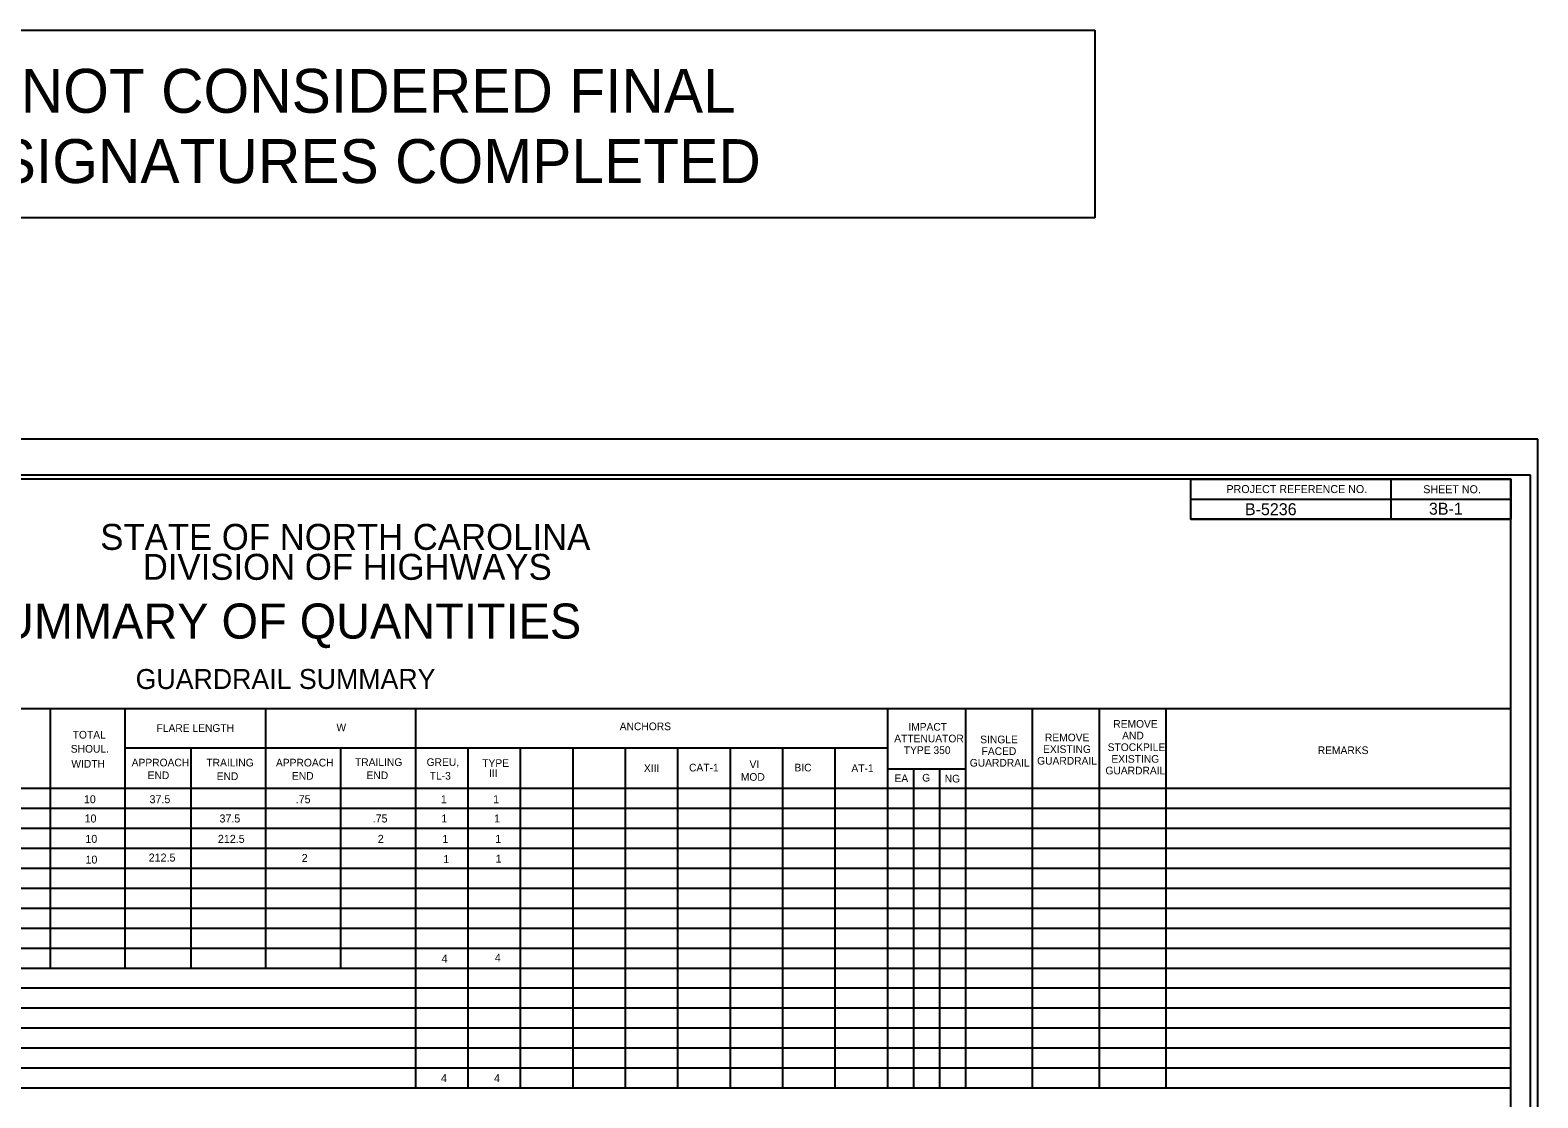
# Model space of a CAD drawing. Extents: x 9833 to 11517, y 9975 to 11331.
# Drawn here: x 10574 to 11517, y 10663 to 11331 of the extents above; entities that cross this region are included whole.
import ezdxf

# ---------------------------------------------------------------- set-up
doc = ezdxf.new("R2010")
doc.units = 0
for name, color, linetype in [('Old_Level_1', 7, 'Continuous'), ('Prop Dimension Text', 7, 'Continuous'), ('Sheet Cutting Line CELL', 7, 'Continuous'), ('Sheet Data Field CELL', 7, 'Continuous'), ('Sheet Plot Border Inside CELL', 7, 'Continuous'), ('Sheet Plot Border Outside CELL', 7, 'Continuous'), ('Sheet Sticker Exception Certification CELL', 7, 'Continuous'), ('Sheet Summary CELL', 7, 'Continuous'), ('Sheet Summary Combination CELL', 7, 'Continuous'), ('Sheet Summary Combination Grid CELL', 7, 'Continuous')]:
    doc.layers.add(name, color=color, linetype=linetype)

msp = doc.modelspace()

# ---------------------------------------------------------------- linework, layer by layer
at = {"layer": 'Sheet Cutting Line CELL'}
msp.add_line((11517, 11075), (9833, 11075), dxfattribs=at)
at = {"layer": 'Sheet Plot Border Inside CELL'}
msp.add_lwpolyline([(11512.5, 11052.55), (9846, 11052.55), (9846, 9997.45), (11512.5, 9997.45)], close=True, dxfattribs=at)
at = {"layer": 'Sheet Plot Border Outside CELL'}
msp.add_lwpolyline([(11517, 11075), (9833, 11075), (9833, 9975), (11517, 9975)], close=True, dxfattribs=at)
at = {"layer": 'Sheet Sticker Exception Certification CELL'}
for p, q in [((10239.6, 11331.02), (11239.78, 11331.02)), ((11239.78, 11330.96), (11239.78, 11213.46)), ((11239.78, 11213.52), (10239.6, 11213.52))]:
    msp.add_line(p, q, dxfattribs=at)
at = {"layer": 'Sheet Summary CELL'}
for p, q in [((11425, 11049.95), (11425, 11024.95)), ((11299.95, 11037.45), (11500, 11037.45)), ((11299.95, 11024.95), (11500, 11024.95)), ((10749.6, 10961.2), (10749.6, 10961.2))]:
    msp.add_line(p, q, dxfattribs=at)
for points in [[(11500, 11050), (10000, 11050), (10000, 10000), (11500, 10000)], [(11299.95, 11050), (11500, 11050), (11500, 11024.95), (11299.95, 11024.95)]]:
    msp.add_lwpolyline(points, close=True, dxfattribs=at)
at = {"layer": 'Sheet Summary Combination Grid CELL'}
for p, q in [((10000, 10906.54), (11500, 10906.54)), ((10585.95, 10906.54), (10585.95, 10744.04)), ((10632.8, 10906.54), (10632.8, 10744.04)), ((10720.9, 10906.54), (10720.9, 10744.04)), ((10814.65, 10906.54), (10814.65, 10669.04)), ((11109.95, 10906.54), (11109.95, 10669.04)), ((11158.8, 10906.54), (11158.8, 10669.04)), ((11200.6, 10906.54), (11200.6, 10669.04)), ((11242.4, 10906.54), (11242.4, 10669.04)), ((11284.25, 10906.54), (11284.25, 10669.04)), ((11109.95, 10881.54), (10632.8, 10881.54)), ((10674, 10881.54), (10674, 10744.04)), ((10767.75, 10881.54), (10767.75, 10744.04)), ((10847.45, 10881.54), (10847.45, 10669.04)), ((10880.25, 10881.54), (10880.25, 10669.04)), ((10913.1, 10881.54), (10913.1, 10669.04)), ((10945.9, 10881.54), (10945.9, 10669.04)), ((10978.7, 10881.54), (10978.7, 10669.04)), ((11011.5, 10881.54), (11011.5, 10669.04)), ((11044.35, 10881.54), (11044.35, 10669.04)), ((11077.15, 10881.54), (11077.15, 10669.04)), ((11109.95, 10868.79), (11158.55, 10868.79)), ((11126.2, 10868.79), (11126.31, 10669.04)), ((11142.55, 10868.79), (11142.66, 10669.04)), ((10000, 10856.54), (11500, 10856.54)), ((10000, 10844.04), (11500, 10844.04)), ((10000, 10831.54), (11500, 10831.54)), ((10000, 10819.04), (11500, 10819.04)), ((10000, 10806.54), (11500, 10806.54)), ((10000, 10794.04), (11500, 10794.04)), ((10000, 10781.54), (11500, 10781.54)), ((10000, 10769.04), (11500, 10769.04)), ((10000, 10756.54), (11500, 10756.54)), ((10000, 10744.04), (11500, 10744.04)), ((10000, 10731.54), (11500, 10731.54)), ((10000, 10719.04), (11500, 10719.04)), ((10000, 10706.54), (11500, 10706.54)), ((10000, 10694.04), (11500, 10694.04)), ((10000, 10681.54), (11500, 10681.54)), ((10000, 10669.04), (11500, 10669.04))]:
    msp.add_line(p, q, dxfattribs=at)

# ---------------------------------------------------------------- texts
at = {"layer": 'Old_Level_1'}
for s, p in [('10', (10607.14, 10847.18)), ('37.5', (10648.24, 10847.18)), ('.75', (10739.71, 10847.18)), ('1', (10830.52, 10847.18)), ('1', (10863.26, 10847.18)), ('10', (10607.59, 10835.13)), ('37.5', (10692.01, 10835.13)), ('.75', (10787.85, 10835.13)), ('1', (10830.83, 10835.13)), ('1', (10863.84, 10835.13)), ('10', (10608.08, 10822.38)), ('212.5', (10691.02, 10822.38)), ('2', (10791.06, 10822.38)), ('1', (10831.48, 10822.38)), ('1', (10864.54, 10822.38))]:
    msp.add_text(s, height=5, dxfattribs=at).set_placement(p)
at = {"layer": 'Prop Dimension Text'}
for s, p in [('10', (10608.15, 10809.4)), ('212.5', (10647.72, 10810.69)), ('2', (10743.45, 10810.41)), ('1', (10832.03, 10809.68)), ('1', (10864.82, 10809.97)), ('4', (10830.98, 10747.48)), ('4', (10864.33, 10748.04)), ('4', (10830.6, 10672.61)), ('4', (10863.81, 10672.61))]:
    msp.add_text(s, height=5, dxfattribs=at).set_placement(p)
at = {"layer": 'Sheet Data Field CELL'}
for s, p in [('B-5236   ', (11333.69, 11027.45)), ('3B-1 ', (11448.82, 11027.75))]:
    msp.add_text(s, height=7.5, dxfattribs=at).set_placement(p)
at = {"layer": 'Sheet Sticker Exception Certification CELL'}
for s, p in [('DOCUMENT NOT CONSIDERED FINAL', (10344.95, 11279.3)), ('UNLESS ALL SIGNATURES COMPLETED', (10319.59, 11235.3))]:
    msp.add_text(s, height=27.5, dxfattribs=at).set_placement(p)
at = {"layer": 'Sheet Summary CELL'}
for s, height, p in [('PROJECT REFERENCE NO.', 5.0001, (11322.15, 11041.3)), ('SHEET NO.', 5, (11445.3, 11041.2)), ('STATE OF NORTH CAROLINA', 16.2501, (10617.4, 11005.75)), ('DIVISION OF HIGHWAYS', 16.2501, (10644, 10987)), ('SUMMARY OF QUANTITIES', 21.9501, (10535.11, 10950.22))]:
    msp.add_text(s, height=height, dxfattribs=at).set_placement(p)
at = {"layer": 'Sheet Summary Combination CELL'}
msp.add_text('GUARDRAIL SUMMARY', height=12.5001, rotation=0.01193, dxfattribs=at).set_placement((10639.54, 10918.66))
for s, p in [('ANCHORS', (10942.45, 10892.89)), ('IMPACT', (11123.05, 10892.59)), ('REMOVE', (11251.3, 10894.44)), ('TOTAL', (10600.15, 10887.64)), ('FLARE LENGTH', (10652.6, 10891.84)), ('W', (10765.2, 10892.24)), ('ATTENUATOR', (11114.25, 10885.29)), ('SINGLE', (11168.05, 10884.69)), ('REMOVE', (11208.55, 10885.94)), ('AND', (11256.85, 10887.14)), ('SHOUL.', (10598.95, 10878.84)), ('TYPE 350', (11120.25, 10877.99)), ('FACED', (11168.9, 10877.39)), ('EXISTING', (11207.35, 10878.64)), ('STOCKPILE', (11247.8, 10879.84)), ('REMARKS', (11379.25, 10877.94)), ('WIDTH', (10599.3, 10869.44)), ('APPROACH', (10637.05, 10870.24)), ('TRAILING', (10683.8, 10870.19)), ('APPROACH', (10727.35, 10870.19)), ('TRAILING', (10776.8, 10870.49)), ('GREU,', (10821.62, 10870.49)), ('TYPE', (10856.44, 10869.88)), ('XIII', (10957.6, 10866.74)), ('CAT-1', (10985.85, 10867.09)), ('VI', (11023.7, 10869.14)), ('BIC', (11051.8, 10867.09)), ('AT-1', (11087.45, 10866.69)), ('GUARDRAIL', (11161.5, 10870.09)), ('GUARDRAIL', (11203.65, 10871.34)), ('GUARDRAIL', (11246.4, 10865.24)), ('EXISTING', (11250.1, 10872.54)), ('END', (10647.05, 10862.24)), ('END', (10690.25, 10861.69)), ('END', (10737.35, 10861.89)), ('END', (10784, 10862.24)), ('TL-3', (10823.57, 10861.94)), ('III', (10860.66, 10863.59)), ('MOD', (11018.25, 10861.24)), ('EA', (11114.4, 10860.39)), ('G', (11131.75, 10860.74)), ('NG', (11145.8, 10860.19))]:
    msp.add_text(s, height=4.8, dxfattribs=at).set_placement(p)

doc.saveas('drawing.dxf')
